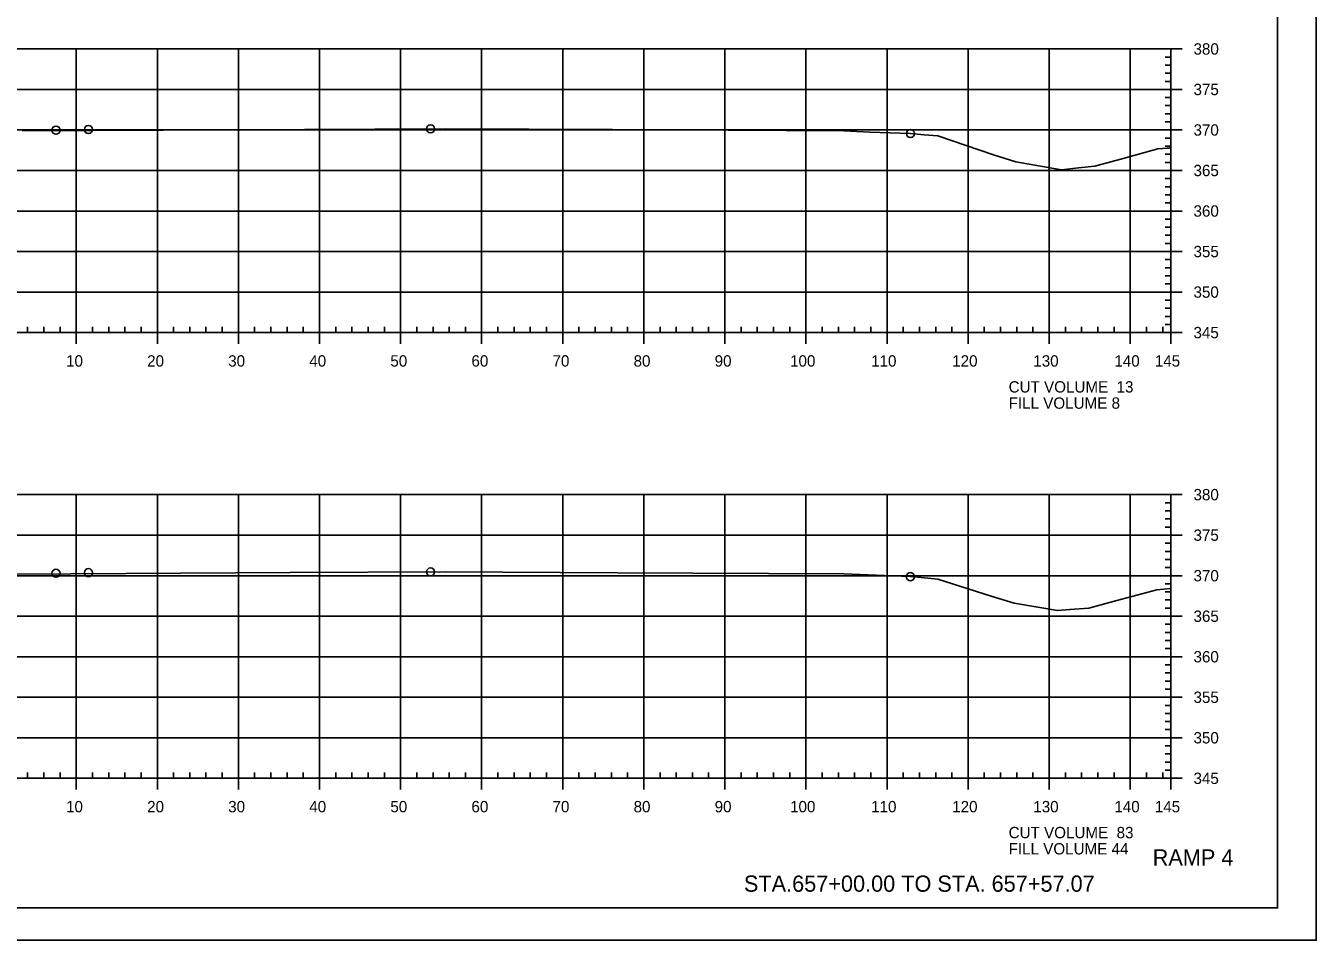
# Model space of a CAD drawing. Extents: x 1359801 to 1362404, y 372415 to 374228.
# Drawn here: x 1361823.7 to 1361982.8, y 372947.9 to 373060.8 of the extents above; entities that cross this region are included whole.
import ezdxf

# ---------------------------------------------------------------- set-up
doc = ezdxf.new("R2010")
doc.units = 0
for name, color, linetype in [('S_DRG_PT_SYM', 7, 'Continuous'), ('S_MAILBOX', 7, 'Continuous'), ('S_PRIMARY_CTL', 7, 'Continuous'), ('S_SHOULDER', 7, 'Continuous'), ('S_SIGN', 7, 'Continuous'), ('S_UTL_PT_SYM', 7, 'Continuous'), ('S_WATER_UTILITIES', 7, 'Continuous')]:
    doc.layers.add(name, color=color, linetype=linetype)

msp = doc.modelspace()

# ---------------------------------------------------------------- linework, layer by layer
at = {"layer": 'S_DRG_PT_SYM'}
for points in [[(1361823.23, 373047.8), (1361875.43, 373048.07), (1361896.04, 373047.96), (1361924.58, 373047.8), (1361927.78, 373047.67), (1361932.78, 373047.48), (1361934.46, 373047.34), (1361936.15, 373047.2), (1361943.04, 373044.87), (1361945.76, 373044), (1361948.11, 373043.58), (1361951.42, 373042.99), (1361953.51, 373043.25), (1361955.51, 373043.45), (1361959.02, 373044.41), (1361963.29, 373045.59), (1361964.46, 373045.67), (1361964.89, 373045.69)], [(1361822.49, 372993.12), (1361856.28, 372993.3), (1361875.39, 372993.4), (1361896.66, 372993.28), (1361924.57, 372993.13), (1361930.55, 372992.89), (1361932.77, 372992.8), (1361934.11, 372992.69), (1361936.15, 372992.49), (1361942.75, 372990.38), (1361945.58, 372989.54), (1361948.73, 372989), (1361950.91, 372988.61), (1361952.44, 372988.75), (1361954.79, 372988.92), (1361958.24, 372989.85), (1361963.16, 372991.19), (1361964.89, 372991.33)]]:
    msp.add_lwpolyline(points, dxfattribs=at)
at = {"layer": 'S_MAILBOX'}
for p, q in [((1361674.89, 373057.92), (1361964.89, 373057.92)), ((1361829.89, 373022.92), (1361829.89, 373057.92)), ((1361839.89, 373022.92), (1361839.89, 373057.92)), ((1361849.89, 373022.92), (1361849.89, 373057.92)), ((1361859.89, 373022.92), (1361859.89, 373057.92)), ((1361869.89, 373022.92), (1361869.89, 373057.92)), ((1361879.89, 373022.92), (1361879.89, 373057.92)), ((1361889.89, 373022.92), (1361889.89, 373057.92)), ((1361899.89, 373022.92), (1361899.89, 373057.92)), ((1361909.89, 373022.92), (1361909.89, 373057.92)), ((1361919.89, 373022.92), (1361919.89, 373057.92)), ((1361929.89, 373022.92), (1361929.89, 373057.92)), ((1361939.89, 373022.92), (1361939.89, 373057.92)), ((1361949.89, 373022.92), (1361949.89, 373057.92)), ((1361959.89, 373022.92), (1361959.89, 373057.92)), ((1361964.89, 373022.92), (1361964.89, 373057.92)), ((1361674.89, 373052.92), (1361964.89, 373052.92)), ((1361674.89, 373047.92), (1361964.89, 373047.92)), ((1361674.89, 373042.92), (1361964.89, 373042.92)), ((1361674.89, 373037.92), (1361964.89, 373037.92)), ((1361674.89, 373032.92), (1361964.89, 373032.92)), ((1361674.89, 373027.92), (1361964.89, 373027.92)), ((1361674.89, 373022.92), (1361964.89, 373022.92)), ((1361674.89, 373002.92), (1361964.89, 373002.92)), ((1361829.89, 372967.92), (1361829.89, 373002.92)), ((1361839.89, 372967.92), (1361839.89, 373002.92)), ((1361849.89, 372967.92), (1361849.89, 373002.92)), ((1361859.89, 372967.92), (1361859.89, 373002.92)), ((1361869.89, 372967.92), (1361869.89, 373002.92)), ((1361879.89, 372967.92), (1361879.89, 373002.92)), ((1361889.89, 372967.92), (1361889.89, 373002.92)), ((1361899.89, 372967.92), (1361899.89, 373002.92)), ((1361909.89, 372967.92), (1361909.89, 373002.92)), ((1361919.89, 372967.92), (1361919.89, 373002.92)), ((1361929.89, 372967.92), (1361929.89, 373002.92)), ((1361939.89, 372967.92), (1361939.89, 373002.92)), ((1361949.89, 372967.92), (1361949.89, 373002.92)), ((1361959.89, 372967.92), (1361959.89, 373002.92)), ((1361964.89, 372967.92), (1361964.89, 373002.92)), ((1361674.89, 372997.92), (1361964.89, 372997.92)), ((1361674.89, 372992.92), (1361964.89, 372992.92)), ((1361674.89, 372987.92), (1361964.89, 372987.92)), ((1361674.89, 372982.92), (1361964.89, 372982.92)), ((1361674.89, 372977.92), (1361964.89, 372977.92)), ((1361674.89, 372972.92), (1361964.89, 372972.92)), ((1361674.89, 372967.92), (1361964.89, 372967.92))]:
    msp.add_line(p, q, dxfattribs=at)
at = {"layer": 'S_SHOULDER'}
msp.add_line((1361649.49, 372947.94), (1361982.82, 372947.94), dxfattribs=at)
for points in [[(1361649.48, 373161.28), (1361982.82, 373161.28), (1361982.82, 372947.94), (1361649.48, 372947.94)], [(1361895.81, 373157.38), (1361895.81, 373147.5), (1361931.54, 373147.5), (1361931.54, 373144.58), (1361954.74, 373144.58), (1361954.74, 373120.25), (1361978.07, 373120.25), (1361978.07, 372951.92), (1361661.89, 372951.92), (1361661.89, 373157.38)]]:
    msp.add_lwpolyline(points, close=True, dxfattribs=at)
for centre in [(1361827.39, 373047.9), (1361831.39, 373047.98), (1361873.59, 373048.06), (1361932.78, 373047.48), (1361827.39, 372993.22), (1361831.39, 372993.3), (1361873.59, 372993.39), (1361932.77, 372992.8)]:
    msp.add_circle(centre, 0.5, dxfattribs=at)
at = {"layer": 'S_UTL_PT_SYM'}
for q in [(1361978.07, 373157.38), (1361661.89, 372951.92)]:
    msp.add_line((1361978.07, 372951.92), q, dxfattribs=at)
at = {"layer": 'S_WATER_UTILITIES'}
for p, q in [((1361964.89, 373022.92), (1361964.89, 373057.92)), ((1361966.29, 373057.92), (1361964.89, 373057.92)), ((1361964.89, 373056.92), (1361964.19, 373056.92)), ((1361964.89, 373055.92), (1361964.19, 373055.92)), ((1361964.89, 373054.92), (1361964.19, 373054.92)), ((1361964.89, 373053.92), (1361964.19, 373053.92)), ((1361964.89, 373051.92), (1361964.19, 373051.92)), ((1361966.29, 373052.92), (1361964.89, 373052.92)), ((1361964.89, 373050.92), (1361964.19, 373050.92)), ((1361964.89, 373049.92), (1361964.19, 373049.92)), ((1361964.89, 373048.92), (1361964.19, 373048.92)), ((1361964.89, 373046.92), (1361964.19, 373046.92)), ((1361966.29, 373047.92), (1361964.89, 373047.92)), ((1361964.89, 373045.92), (1361964.19, 373045.92)), ((1361964.89, 373044.92), (1361964.19, 373044.92)), ((1361964.89, 373043.92), (1361964.19, 373043.92)), ((1361964.89, 373041.92), (1361964.19, 373041.92)), ((1361966.29, 373042.92), (1361964.89, 373042.92)), ((1361964.89, 373040.92), (1361964.19, 373040.92)), ((1361964.89, 373039.92), (1361964.19, 373039.92)), ((1361964.89, 373038.92), (1361964.19, 373038.92)), ((1361966.29, 373037.92), (1361964.89, 373037.92)), ((1361964.89, 373036.92), (1361964.19, 373036.92)), ((1361964.89, 373035.92), (1361964.19, 373035.92)), ((1361964.89, 373034.92), (1361964.19, 373034.92)), ((1361964.89, 373033.92), (1361964.19, 373033.92)), ((1361966.29, 373032.92), (1361964.89, 373032.92)), ((1361964.89, 373031.92), (1361964.19, 373031.92)), ((1361964.89, 373030.92), (1361964.19, 373030.92)), ((1361964.89, 373029.92), (1361964.19, 373029.92)), ((1361964.89, 373028.92), (1361964.19, 373028.92)), ((1361966.29, 373027.92), (1361964.89, 373027.92)), ((1361964.89, 373026.92), (1361964.19, 373026.92)), ((1361964.89, 373025.92), (1361964.19, 373025.92)), ((1361964.89, 373024.92), (1361964.19, 373024.92)), ((1361674.89, 373022.92), (1361964.89, 373022.92)), ((1361823.89, 373022.92), (1361823.89, 373023.62)), ((1361825.89, 373022.92), (1361825.89, 373023.62)), ((1361827.89, 373022.92), (1361827.89, 373023.62)), ((1361829.89, 373021.52), (1361829.89, 373022.92)), ((1361831.89, 373022.92), (1361831.89, 373023.62)), ((1361833.89, 373022.92), (1361833.89, 373023.62)), ((1361835.89, 373022.92), (1361835.89, 373023.62)), ((1361837.89, 373022.92), (1361837.89, 373023.62)), ((1361839.89, 373021.52), (1361839.89, 373022.92)), ((1361841.89, 373022.92), (1361841.89, 373023.62)), ((1361843.89, 373022.92), (1361843.89, 373023.62)), ((1361845.89, 373022.92), (1361845.89, 373023.62)), ((1361847.89, 373022.92), (1361847.89, 373023.62)), ((1361849.89, 373021.52), (1361849.89, 373022.92)), ((1361851.89, 373022.92), (1361851.89, 373023.62)), ((1361853.89, 373022.92), (1361853.89, 373023.62)), ((1361855.89, 373022.92), (1361855.89, 373023.62)), ((1361857.89, 373022.92), (1361857.89, 373023.62)), ((1361859.89, 373021.52), (1361859.89, 373022.92)), ((1361861.89, 373022.92), (1361861.89, 373023.62)), ((1361863.89, 373022.92), (1361863.89, 373023.62)), ((1361865.89, 373022.92), (1361865.89, 373023.62)), ((1361867.89, 373022.92), (1361867.89, 373023.62)), ((1361869.89, 373021.52), (1361869.89, 373022.92)), ((1361871.89, 373022.92), (1361871.89, 373023.62)), ((1361873.89, 373022.92), (1361873.89, 373023.62)), ((1361875.89, 373022.92), (1361875.89, 373023.62)), ((1361877.89, 373022.92), (1361877.89, 373023.62)), ((1361879.89, 373021.52), (1361879.89, 373022.92)), ((1361881.89, 373022.92), (1361881.89, 373023.62)), ((1361883.89, 373022.92), (1361883.89, 373023.62)), ((1361885.89, 373022.92), (1361885.89, 373023.62)), ((1361887.89, 373022.92), (1361887.89, 373023.62)), ((1361889.89, 373021.52), (1361889.89, 373022.92)), ((1361891.89, 373022.92), (1361891.89, 373023.62)), ((1361893.89, 373022.92), (1361893.89, 373023.62)), ((1361895.89, 373022.92), (1361895.89, 373023.62)), ((1361897.89, 373022.92), (1361897.89, 373023.62)), ((1361899.89, 373021.52), (1361899.89, 373022.92)), ((1361901.89, 373022.92), (1361901.89, 373023.62)), ((1361903.89, 373022.92), (1361903.89, 373023.62)), ((1361905.89, 373022.92), (1361905.89, 373023.62)), ((1361907.89, 373022.92), (1361907.89, 373023.62)), ((1361909.89, 373021.52), (1361909.89, 373022.92)), ((1361911.89, 373022.92), (1361911.89, 373023.62)), ((1361913.89, 373022.92), (1361913.89, 373023.62)), ((1361915.89, 373022.92), (1361915.89, 373023.62)), ((1361917.89, 373022.92), (1361917.89, 373023.62)), ((1361919.89, 373021.52), (1361919.89, 373022.92)), ((1361921.89, 373022.92), (1361921.89, 373023.62)), ((1361923.89, 373022.92), (1361923.89, 373023.62)), ((1361925.89, 373022.92), (1361925.89, 373023.62)), ((1361927.89, 373022.92), (1361927.89, 373023.62)), ((1361929.89, 373021.52), (1361929.89, 373022.92)), ((1361931.89, 373022.92), (1361931.89, 373023.62)), ((1361933.89, 373022.92), (1361933.89, 373023.62)), ((1361935.89, 373022.92), (1361935.89, 373023.62)), ((1361937.89, 373022.92), (1361937.89, 373023.62)), ((1361939.89, 373021.52), (1361939.89, 373022.92)), ((1361941.89, 373022.92), (1361941.89, 373023.62)), ((1361943.89, 373022.92), (1361943.89, 373023.62)), ((1361945.89, 373022.92), (1361945.89, 373023.62)), ((1361947.89, 373022.92), (1361947.89, 373023.62)), ((1361949.89, 373021.52), (1361949.89, 373022.92)), ((1361951.89, 373022.92), (1361951.89, 373023.62)), ((1361953.89, 373022.92), (1361953.89, 373023.62)), ((1361955.89, 373022.92), (1361955.89, 373023.62)), ((1361957.89, 373022.92), (1361957.89, 373023.62)), ((1361959.89, 373021.52), (1361959.89, 373022.92)), ((1361961.89, 373022.92), (1361961.89, 373023.62)), ((1361963.89, 373022.92), (1361963.89, 373023.62)), ((1361964.89, 373023.92), (1361964.19, 373023.92)), ((1361964.89, 373021.52), (1361964.89, 373022.92)), ((1361966.29, 373022.92), (1361964.89, 373022.92)), ((1361964.89, 372967.92), (1361964.89, 373002.92)), ((1361966.29, 373002.92), (1361964.89, 373002.92)), ((1361964.89, 373001.92), (1361964.19, 373001.92)), ((1361964.89, 373000.92), (1361964.19, 373000.92)), ((1361964.89, 372999.92), (1361964.19, 372999.92)), ((1361964.89, 372998.92), (1361964.19, 372998.92)), ((1361966.29, 372997.92), (1361964.89, 372997.92)), ((1361964.89, 372996.92), (1361964.19, 372996.92)), ((1361964.89, 372995.92), (1361964.19, 372995.92)), ((1361964.89, 372994.92), (1361964.19, 372994.92)), ((1361964.89, 372993.92), (1361964.19, 372993.92)), ((1361966.29, 372992.92), (1361964.89, 372992.92)), ((1361964.89, 372991.92), (1361964.19, 372991.92)), ((1361964.89, 372990.92), (1361964.19, 372990.92)), ((1361964.89, 372989.92), (1361964.19, 372989.92)), ((1361964.89, 372988.92), (1361964.19, 372988.92)), ((1361966.29, 372987.92), (1361964.89, 372987.92)), ((1361964.89, 372986.92), (1361964.19, 372986.92)), ((1361964.89, 372985.92), (1361964.19, 372985.92)), ((1361964.89, 372984.92), (1361964.19, 372984.92)), ((1361964.89, 372983.92), (1361964.19, 372983.92)), ((1361964.89, 372981.92), (1361964.19, 372981.92)), ((1361966.29, 372982.92), (1361964.89, 372982.92)), ((1361964.89, 372980.92), (1361964.19, 372980.92)), ((1361964.89, 372979.92), (1361964.19, 372979.92)), ((1361964.89, 372978.92), (1361964.19, 372978.92)), ((1361964.89, 372976.92), (1361964.19, 372976.92)), ((1361966.29, 372977.92), (1361964.89, 372977.92)), ((1361964.89, 372975.92), (1361964.19, 372975.92)), ((1361964.89, 372974.92), (1361964.19, 372974.92)), ((1361964.89, 372973.92), (1361964.19, 372973.92)), ((1361964.89, 372971.92), (1361964.19, 372971.92)), ((1361966.29, 372972.92), (1361964.89, 372972.92)), ((1361964.89, 372970.92), (1361964.19, 372970.92)), ((1361964.89, 372969.92), (1361964.19, 372969.92)), ((1361964.89, 372968.92), (1361964.19, 372968.92)), ((1361674.89, 372967.92), (1361964.89, 372967.92)), ((1361823.89, 372967.92), (1361823.89, 372968.62)), ((1361825.89, 372967.92), (1361825.89, 372968.62)), ((1361827.89, 372967.92), (1361827.89, 372968.62)), ((1361829.89, 372966.52), (1361829.89, 372967.92)), ((1361831.89, 372967.92), (1361831.89, 372968.62)), ((1361833.89, 372967.92), (1361833.89, 372968.62)), ((1361835.89, 372967.92), (1361835.89, 372968.62)), ((1361837.89, 372967.92), (1361837.89, 372968.62)), ((1361839.89, 372966.52), (1361839.89, 372967.92)), ((1361841.89, 372967.92), (1361841.89, 372968.62)), ((1361843.89, 372967.92), (1361843.89, 372968.62)), ((1361845.89, 372967.92), (1361845.89, 372968.62)), ((1361847.89, 372967.92), (1361847.89, 372968.62)), ((1361849.89, 372966.52), (1361849.89, 372967.92)), ((1361851.89, 372967.92), (1361851.89, 372968.62)), ((1361853.89, 372967.92), (1361853.89, 372968.62)), ((1361855.89, 372967.92), (1361855.89, 372968.62)), ((1361857.89, 372967.92), (1361857.89, 372968.62)), ((1361859.89, 372966.52), (1361859.89, 372967.92)), ((1361861.89, 372967.92), (1361861.89, 372968.62)), ((1361863.89, 372967.92), (1361863.89, 372968.62)), ((1361865.89, 372967.92), (1361865.89, 372968.62)), ((1361867.89, 372967.92), (1361867.89, 372968.62)), ((1361869.89, 372966.52), (1361869.89, 372967.92)), ((1361871.89, 372967.92), (1361871.89, 372968.62)), ((1361873.89, 372967.92), (1361873.89, 372968.62)), ((1361875.89, 372967.92), (1361875.89, 372968.62)), ((1361877.89, 372967.92), (1361877.89, 372968.62)), ((1361879.89, 372966.52), (1361879.89, 372967.92)), ((1361881.89, 372967.92), (1361881.89, 372968.62)), ((1361883.89, 372967.92), (1361883.89, 372968.62)), ((1361885.89, 372967.92), (1361885.89, 372968.62)), ((1361887.89, 372967.92), (1361887.89, 372968.62)), ((1361889.89, 372966.52), (1361889.89, 372967.92)), ((1361891.89, 372967.92), (1361891.89, 372968.62)), ((1361893.89, 372967.92), (1361893.89, 372968.62)), ((1361895.89, 372967.92), (1361895.89, 372968.62)), ((1361897.89, 372967.92), (1361897.89, 372968.62)), ((1361899.89, 372966.52), (1361899.89, 372967.92)), ((1361901.89, 372967.92), (1361901.89, 372968.62)), ((1361903.89, 372967.92), (1361903.89, 372968.62)), ((1361905.89, 372967.92), (1361905.89, 372968.62)), ((1361907.89, 372967.92), (1361907.89, 372968.62)), ((1361909.89, 372966.52), (1361909.89, 372967.92)), ((1361911.89, 372967.92), (1361911.89, 372968.62)), ((1361913.89, 372967.92), (1361913.89, 372968.62)), ((1361915.89, 372967.92), (1361915.89, 372968.62)), ((1361917.89, 372967.92), (1361917.89, 372968.62)), ((1361919.89, 372966.52), (1361919.89, 372967.92)), ((1361921.89, 372967.92), (1361921.89, 372968.62)), ((1361923.89, 372967.92), (1361923.89, 372968.62)), ((1361925.89, 372967.92), (1361925.89, 372968.62)), ((1361927.89, 372967.92), (1361927.89, 372968.62)), ((1361929.89, 372966.52), (1361929.89, 372967.92)), ((1361931.89, 372967.92), (1361931.89, 372968.62)), ((1361933.89, 372967.92), (1361933.89, 372968.62)), ((1361935.89, 372967.92), (1361935.89, 372968.62)), ((1361937.89, 372967.92), (1361937.89, 372968.62)), ((1361939.89, 372966.52), (1361939.89, 372967.92)), ((1361941.89, 372967.92), (1361941.89, 372968.62)), ((1361943.89, 372967.92), (1361943.89, 372968.62)), ((1361945.89, 372967.92), (1361945.89, 372968.62)), ((1361947.89, 372967.92), (1361947.89, 372968.62)), ((1361949.89, 372966.52), (1361949.89, 372967.92)), ((1361951.89, 372967.92), (1361951.89, 372968.62)), ((1361953.89, 372967.92), (1361953.89, 372968.62)), ((1361955.89, 372967.92), (1361955.89, 372968.62)), ((1361957.89, 372967.92), (1361957.89, 372968.62)), ((1361959.89, 372966.52), (1361959.89, 372967.92)), ((1361961.89, 372967.92), (1361961.89, 372968.62)), ((1361963.89, 372967.92), (1361963.89, 372968.62)), ((1361964.89, 372966.52), (1361964.89, 372967.92)), ((1361966.29, 372967.92), (1361964.89, 372967.92))]:
    msp.add_line(p, q, dxfattribs=at)

# ---------------------------------------------------------------- texts
at = {"layer": 'S_PRIMARY_CTL'}
for s, p in [('380', (1361967.69, 373057.22)), ('375', (1361967.69, 373052.22)), ('370', (1361967.69, 373047.22)), ('365', (1361967.69, 373042.22)), ('360', (1361967.69, 373037.22)), ('355', (1361967.69, 373032.22)), ('350', (1361967.69, 373027.22)), ('345', (1361967.69, 373022.22)), ('10', (1361828.63, 373018.72)), ('20', (1361838.63, 373018.72)), ('30', (1361848.63, 373018.72)), ('40', (1361858.63, 373018.72)), ('50', (1361868.63, 373018.72)), ('60', (1361878.63, 373018.72)), ('70', (1361888.63, 373018.72)), ('80', (1361898.63, 373018.72)), ('90', (1361908.63, 373018.72)), ('100', (1361917.93, 373018.72)), ('110', (1361927.93, 373018.72)), ('120', (1361937.93, 373018.72)), ('130', (1361947.93, 373018.72)), ('140', (1361957.93, 373018.72)), ('145', (1361962.92, 373018.72)), ('CUT VOLUME  13', (1361944.89, 373015.52)), ('FILL VOLUME 8', (1361944.89, 373013.52)), ('380', (1361967.69, 373002.22)), ('375', (1361967.69, 372997.22)), ('370', (1361967.69, 372992.22)), ('365', (1361967.69, 372987.22)), ('360', (1361967.69, 372982.22)), ('355', (1361967.69, 372977.22)), ('350', (1361967.69, 372972.22)), ('345', (1361967.69, 372967.22)), ('10', (1361828.63, 372963.72)), ('20', (1361838.63, 372963.72)), ('30', (1361848.63, 372963.72)), ('40', (1361858.63, 372963.72)), ('50', (1361868.63, 372963.72)), ('60', (1361878.63, 372963.72)), ('70', (1361888.63, 372963.72)), ('80', (1361898.63, 372963.72)), ('90', (1361908.63, 372963.72)), ('100', (1361917.93, 372963.72)), ('110', (1361927.93, 372963.72)), ('120', (1361937.93, 372963.72)), ('130', (1361947.93, 372963.72)), ('140', (1361957.93, 372963.72)), ('145', (1361962.92, 372963.72)), ('CUT VOLUME  83', (1361944.89, 372960.52)), ('FILL VOLUME 44', (1361944.89, 372958.52))]:
    msp.add_text(s, height=1.4, dxfattribs=at).set_placement(p)
at = {"layer": 'S_SHOULDER'}
for p in [(1361924.54, 373047.75), (1361924.52, 372993.08)]:
    msp.add_text('+', height=0.1, dxfattribs=at).set_placement(p)
at = {"layer": 'S_SIGN'}
for s, p in [('RAMP 4', (1361962.66, 372957.15)), ('STA.657+00.00 TO STA. 657+57.07', (1361912.24, 372953.92))]:
    msp.add_text(s, height=2, dxfattribs=at).set_placement(p)

doc.saveas('drawing.dxf')
